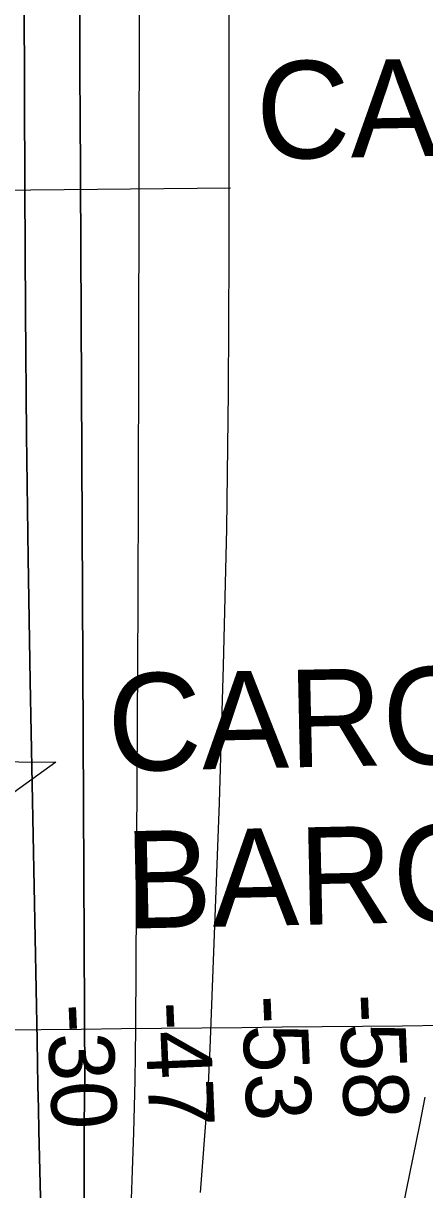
# Model space of a CAD drawing. Extents: x 3651524 to 3689615, y 505651 to 531377.
# Drawn here: x 3658055 to 3658467, y 523045 to 524242 of the extents above; entities that cross this region are included whole.
import ezdxf

# ---------------------------------------------------------------- set-up
doc = ezdxf.new("R2010")
doc.units = 0
for name, color, linetype in [('V-CHAN-NAID', 7, 'Continuous'), ('V-GRID-MAJR', 7, 'Continuous'), ('V-RIVR-RANG', 7, 'Continuous'), ('V-TOPO-DPTH', 7, 'Continuous'), ('V-TOPO-MAJR', 7, 'Continuous'), ('V-TOPO-MINR', 7, 'Continuous')]:
    doc.layers.add(name, color=color, linetype=linetype)

msp = doc.modelspace()

# ---------------------------------------------------------------- linework, layer by layer
at = {"layer": 'V-CHAN-NAID'}
msp.add_lwpolyline([(3658011.684, 523483.916), (3658088.176, 523483.373), (3658025.973, 523438.851)], dxfattribs=at)
at = {"layer": 'V-GRID-MAJR'}
msp.add_spline([(3655639.78, 523183.706), (3660918.553, 523238.605), (3666197.317, 523294.271), (3671476.073, 523350.705), (3676754.821, 523407.907), (3682033.561, 523465.877), (3687312.292, 523524.615)], degree=3, dxfattribs=at)
at = {"layer": 'V-RIVR-RANG'}
msp.add_line((3657267.387, 524062.465), (3658267.333, 524072.838), dxfattribs=at)
at = {"layer": 'V-TOPO-DPTH'}
for points in [[(3658163.339, 525508.497), (3658188.784, 525000.163), (3658189.938, 524888.068), (3658185.201, 524780.54), (3658172.024, 524663.663), (3658172.628, 524551.564), (3658173.334, 524388.632), (3658173.441, 524357.998), (3658173.512, 524327.364), (3658173.53, 524296.729), (3658173.512, 524266.095), (3658172.976, 523891.595), (3658172.707, 523769.096), (3658172.314, 523646.598), (3658171.735, 523524.1), (3658171.031, 523401.603), (3658169.786, 523210.164), (3658169.505, 523183.389), (3658169.082, 523156.617), (3658168.445, 523129.849), (3658167.665, 523103.084), (3658164.114, 522995.797)], [(3658163.339, 525508.497), (3658188.784, 525000.163), (3658189.938, 524888.068), (3658185.201, 524780.54), (3658172.024, 524663.663), (3658172.628, 524551.564), (3658173.334, 524388.632), (3658173.441, 524357.998), (3658173.512, 524327.364), (3658173.53, 524296.729), (3658173.512, 524266.095), (3658172.976, 523891.595), (3658172.707, 523769.096), (3658172.314, 523646.598), (3658171.735, 523524.1), (3658171.031, 523401.603), (3658169.786, 523210.164), (3658169.505, 523183.389), (3658169.082, 523156.617), (3658168.445, 523129.849), (3658167.665, 523103.084), (3658164.114, 522995.797)], [(3658060.189, 525061.553), (3658059.027, 524914.31), (3658057.987, 524767.067), (3658057.03, 524619.823), (3658055.587, 524382.442), (3658055.454, 524353.887), (3658055.377, 524325.333), (3658055.383, 524296.779), (3658055.444, 524268.225), (3658056.148, 524072.311), (3658056.892, 523945.802), (3658058.021, 523819.298), (3658059.728, 523692.801), (3658061.821, 523566.308), (3658068.766, 523197.603), (3658069.223, 523174.408), (3658069.706, 523151.215), (3658070.23, 523128.022), (3658070.781, 523104.83), (3658083.575, 522585.083)], [(3658083.575, 522585.083), (3658070.781, 523104.83), (3658070.23, 523128.022), (3658069.706, 523151.215), (3658069.223, 523174.408), (3658068.766, 523197.603), (3658061.821, 523566.308), (3658059.728, 523692.801), (3658058.021, 523819.298), (3658056.892, 523945.802), (3658056.148, 524072.311), (3658055.444, 524268.225), (3658055.383, 524296.779), (3658055.377, 524325.333), (3658055.454, 524353.887), (3658055.587, 524382.442), (3658057.03, 524619.823), (3658057.987, 524767.067), (3658059.027, 524914.31), (3658060.189, 525061.553)], [(3658112.411, 524268.68), (3658112.555, 524239.867), (3658112.698, 524211.054), (3658112.839, 524182.241), (3658112.98, 524153.428), (3658117.837, 523155.033), (3658117.838, 523154.108), (3658117.802, 523151.333), (3658117.706, 523147.299), (3658117.64, 523144.358), (3658117.578, 523141.416), (3658117.523, 523138.474), (3658117.445, 523133.772), (3658117.393, 523129.949), (3658117.352, 523126.127), (3658117.329, 523122.304), (3658117.317, 523118.482), (3658116.373, 522013.405)], [(3658116.373, 522013.405), (3658117.317, 523118.482), (3658117.329, 523122.304), (3658117.352, 523126.127), (3658117.393, 523129.949), (3658117.445, 523133.772), (3658117.523, 523138.474), (3658117.578, 523141.416), (3658117.64, 523144.358), (3658117.706, 523147.299), (3658117.802, 523151.333), (3658117.838, 523154.108), (3658117.837, 523155.033), (3658112.98, 524153.428), (3658112.839, 524182.241), (3658112.698, 524211.054), (3658112.555, 524239.867), (3658112.411, 524268.68)]]:
    msp.add_lwpolyline(points, dxfattribs=at)
at = {"layer": 'V-TOPO-MAJR'}
msp.add_lwpolyline([(3658318.706, 525006.681), (3658302.377, 524876.413), (3658263.783, 524756.601), (3658263.292, 524616.776), (3658265.262, 524382.34), (3658265.455, 524355.641), (3658265.605, 524328.943), (3658265.692, 524302.244), (3658265.737, 524275.545), (3658265.87, 524004.334), (3658265.149, 523863.577), (3658263.374, 523722.838), (3658260.018, 523582.129), (3658255.609, 523441.439), (3658246.295, 523189.468), (3658245.668, 523174.782), (3658244.93, 523160.102), (3658244.024, 523145.432), (3658243.008, 523130.768), (3658236.32, 523041.684)], dxfattribs=at)
at = {"layer": 'V-TOPO-MINR'}
for points in [[(3658163.339, 525508.497), (3658188.784, 525000.163), (3658189.938, 524888.068), (3658185.201, 524780.54), (3658172.024, 524663.663), (3658172.628, 524551.564), (3658173.334, 524388.632), (3658173.441, 524357.998), (3658173.512, 524327.364), (3658173.53, 524296.729), (3658173.512, 524266.095), (3658172.976, 523891.595), (3658172.707, 523769.096), (3658172.314, 523646.598), (3658171.735, 523524.1), (3658171.031, 523401.603), (3658169.786, 523210.164), (3658169.505, 523183.389), (3658169.082, 523156.617), (3658168.445, 523129.849), (3658167.665, 523103.084), (3658164.114, 522995.797)], [(3658060.189, 525061.553), (3658059.027, 524914.31), (3658057.987, 524767.067), (3658057.03, 524619.823), (3658055.587, 524382.442), (3658055.454, 524353.887), (3658055.377, 524325.333), (3658055.383, 524296.779), (3658055.444, 524268.225), (3658056.148, 524072.311), (3658056.892, 523945.802), (3658058.021, 523819.298), (3658059.728, 523692.801), (3658061.821, 523566.308), (3658068.766, 523197.603), (3658069.223, 523174.408), (3658069.706, 523151.215), (3658070.23, 523128.022), (3658070.781, 523104.83), (3658083.575, 522585.083)], [(3658112.411, 524268.68), (3658112.555, 524239.867), (3658112.698, 524211.054), (3658112.839, 524182.241), (3658112.98, 524153.428), (3658117.837, 523155.033), (3658117.838, 523154.108), (3658117.802, 523151.333), (3658117.706, 523147.299), (3658117.64, 523144.358), (3658117.578, 523141.416), (3658117.523, 523138.474), (3658117.445, 523133.772), (3658117.393, 523129.949), (3658117.352, 523126.127), (3658117.329, 523122.304), (3658117.317, 523118.482), (3658116.373, 522013.405)], [(3658466.908, 523139.302), (3658461.56, 523111.181), (3658433.85, 522975.12)]]:
    msp.add_lwpolyline(points, dxfattribs=at)

# ---------------------------------------------------------------- texts
at = {"layer": 'V-CHAN-NAID'}
for s, rotation, p in [('CARGILL WESTWEGO (103.1)', 1.048979, (3658294.515, 524102.149)), ('CARGILL WESTWEGO', 1.24031, (3658142.086, 523473.824)), ('BARGE SLIP (103.0)', 1.24031, (3658159.99, 523312.361))]:
    msp.add_text(s, height=100, rotation=rotation, dxfattribs=at).set_placement(p)
at = {"layer": 'V-RIVR-RANG'}
for s, p in [('-30', (3658079.021, 523234.397)), ('-47', (3658179.019, 523236.539)), ('-53', (3658278.829, 523243.162)), ('-58', (3658378.86, 523244.513))]:
    msp.add_text(s, height=67, rotation=272.426694, dxfattribs=at).set_placement(p)

doc.saveas('drawing.dxf')
